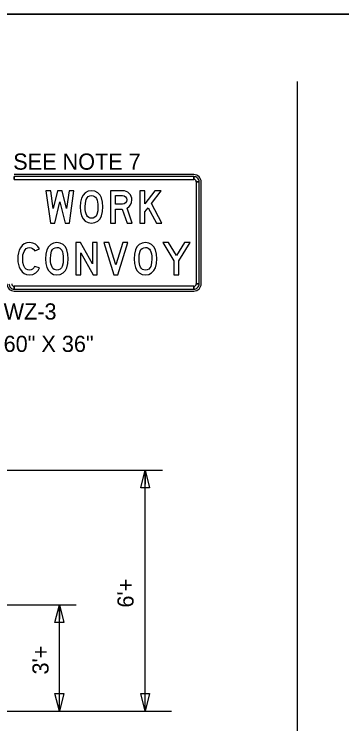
# Model space of a CAD drawing. Extents: x 1374027 to 1374537, y 380415 to 381405.
# Drawn here: x 1374130.82 to 1374142.97, y 381378.88 to 381405.17 of the extents above; entities that cross this region are included whole.
import ezdxf

# ---------------------------------------------------------------- set-up
doc = ezdxf.new("R2010")
doc.units = 0
doc.layers.add('DSN_DRFT_Junk-No-Plot', color=7, linetype='Continuous')
doc.layers.add('Working Level 1', color=7, linetype='Continuous')

msp = doc.modelspace()

# ---------------------------------------------------------------- linework, layer by layer
at = {"layer": 'DSN_DRFT_Junk-No-Plot'}
for points in [[(1374027.083, 381405.174), (1374197.083, 381405.174), (1374197.083, 381295.174), (1374027.083, 381295.174)], [(1374027.083, 381405.174), (1374027.083, 381295.174), (1374197.083, 381295.174), (1374197.083, 381405.174)]]:
    msp.add_lwpolyline(points, close=True, dxfattribs=at)
at = {"layer": 'Working Level 1'}
for p, q in [((1374141.313, 381402.674), (1374141.313, 381297.674)), ((1374137.485, 381399.231), (1374130.825, 381399.231)), ((1374130.825, 381399.051), (1374130.825, 381399.156)), ((1374137.485, 381399.156), (1374137.485, 381399.051)), ((1374137.575, 381398.961), (1374137.679, 381398.961)), ((1374137.754, 381395.181), (1374137.754, 381398.961)), ((1374130.825, 381394.986), (1374130.825, 381395.091)), ((1374137.485, 381395.091), (1374137.485, 381394.986)), ((1374137.679, 381395.181), (1374137.575, 381395.181)), ((1374130.825, 381394.911), (1374137.485, 381394.911)), ((1374129.989, 381388.277), (1374136.317, 381388.277)), ((1374135.68, 381379.345), (1374135.68, 381388.277)), ((1374135.68, 381388.277), (1374135.68, 381387.753)), ((1374130.055, 381383.287), (1374133.116, 381383.287)), ((1374132.499, 381379.345), (1374132.499, 381383.287)), ((1374132.499, 381383.287), (1374132.499, 381382.755)), ((1374118.649, 381379.345), (1374136.66, 381379.345))]:
    msp.add_line(p, q, dxfattribs=at)
for points in [[(1374137.485, 381399.156), (1374130.825, 381399.156), (1374130.825, 381399.051), (1374137.485, 381399.051), (1374137.485, 381399.156)], [(1374137.679, 381395.181), (1374137.679, 381398.961), (1374137.575, 381398.961), (1374137.575, 381395.181), (1374137.679, 381395.181)], [(1374133.041, 381398.631), (1374132.858, 381398.631), (1374132.766, 381397.973), (1374132.607, 381398.631), (1374132.432, 381398.631), (1374132.273, 381397.972), (1374132.182, 381398.631), (1374131.998, 381398.631), (1374132.166, 381397.431), (1374132.33, 381397.431), (1374132.52, 381398.22), (1374132.71, 381397.431), (1374132.873, 381397.431)], [(1374134.111, 381398.031), (1374134.099, 381398.203), (1374134.062, 381398.363), (1374134.008, 381398.471), (1374133.922, 381398.557), (1374133.813, 381398.612), (1374133.691, 381398.631), (1374133.569, 381398.612), (1374133.461, 381398.557), (1374133.376, 381398.471), (1374133.322, 381398.362), (1374133.285, 381398.202), (1374133.273, 381398.031), (1374133.285, 381397.861), (1374133.322, 381397.701), (1374133.376, 381397.592), (1374133.461, 381397.506), (1374133.569, 381397.449), (1374133.691, 381397.431), (1374133.813, 381397.449), (1374133.921, 381397.505), (1374134.007, 381397.59), (1374134.061, 381397.699), (1374134.098, 381397.86)], [(1374135.199, 381397.431), (1374135.01, 381397.991), (1374135.084, 381398.043), (1374135.141, 381398.115), (1374135.178, 381398.201), (1374135.191, 381398.294), (1374135.184, 381398.36), (1374135.166, 381398.422), (1374135.134, 381398.479), (1374135.091, 381398.532), (1374135.038, 381398.575), (1374134.981, 381398.606), (1374134.918, 381398.624), (1374134.851, 381398.631), (1374134.398, 381398.631), (1374134.398, 381397.431), (1374134.579, 381397.431), (1374134.579, 381397.952), (1374134.831, 381397.952), (1374135.008, 381397.431)], [(1374136.299, 381397.431), (1374135.909, 381398.162), (1374136.27, 381398.631), (1374136.041, 381398.631), (1374135.667, 381398.145), (1374135.667, 381398.631), (1374135.486, 381398.631), (1374135.486, 381397.431), (1374135.667, 381397.431), (1374135.667, 381397.848), (1374135.788, 381398.004), (1374136.094, 381397.431)], [(1374133.93, 381398.031), (1374133.919, 381397.885), (1374133.887, 381397.749), (1374133.858, 381397.693), (1374133.813, 381397.649), (1374133.757, 381397.621), (1374133.693, 381397.612), (1374133.637, 381397.618), (1374133.588, 381397.638), (1374133.547, 381397.671), (1374133.514, 381397.717), (1374133.488, 381397.775), (1374133.469, 381397.847), (1374133.458, 381397.932), (1374133.454, 381398.031), (1374133.465, 381398.176), (1374133.497, 381398.311), (1374133.525, 381398.368), (1374133.57, 381398.412), (1374133.627, 381398.44), (1374133.693, 381398.45), (1374133.748, 381398.443), (1374133.796, 381398.423), (1374133.837, 381398.391), (1374133.87, 381398.345), (1374133.896, 381398.286), (1374133.915, 381398.214), (1374133.926, 381398.129)], [(1374134.579, 381398.133), (1374134.579, 381398.45), (1374134.843, 381398.45), (1374134.901, 381398.438), (1374134.95, 381398.403), (1374134.983, 381398.351), (1374134.994, 381398.291), (1374134.983, 381398.23), (1374134.95, 381398.179), (1374134.901, 381398.144), (1374134.843, 381398.133)], [(1374131.759, 381395.777), (1374131.577, 381395.823), (1374131.55, 381395.77), (1374131.506, 381395.729), (1374131.45, 381395.701), (1374131.388, 381395.692), (1374131.325, 381395.701), (1374131.27, 381395.73), (1374131.225, 381395.778), (1374131.188, 381395.845), (1374131.151, 381395.968), (1374131.139, 381396.111), (1374131.151, 381396.254), (1374131.189, 381396.378), (1374131.227, 381396.444), (1374131.274, 381396.491), (1374131.329, 381396.52), (1374131.394, 381396.53), (1374131.453, 381396.521), (1374131.508, 381396.496), (1374131.554, 381396.457), (1374131.585, 381396.407), (1374131.759, 381396.475), (1374131.7, 381396.571), (1374131.614, 381396.646), (1374131.51, 381396.694), (1374131.396, 381396.711), (1374131.291, 381396.698), (1374131.199, 381396.661), (1374131.12, 381396.598), (1374131.054, 381396.511), (1374131.012, 381396.424), (1374130.982, 381396.329), (1374130.964, 381396.224), (1374130.958, 381396.111), (1374130.963, 381395.999), (1374130.981, 381395.895), (1374131.011, 381395.799), (1374131.053, 381395.713), (1374131.117, 381395.624), (1374131.195, 381395.561), (1374131.286, 381395.523), (1374131.39, 381395.511), (1374131.512, 381395.529), (1374131.622, 381395.585), (1374131.708, 381395.67)], [(1374132.827, 381396.111), (1374132.814, 381396.283), (1374132.778, 381396.443), (1374132.724, 381396.551), (1374132.638, 381396.637), (1374132.529, 381396.692), (1374132.407, 381396.711), (1374132.285, 381396.692), (1374132.177, 381396.637), (1374132.092, 381396.551), (1374132.038, 381396.442), (1374132.001, 381396.282), (1374131.989, 381396.111), (1374132.001, 381395.941), (1374132.038, 381395.781), (1374132.092, 381395.672), (1374132.177, 381395.586), (1374132.285, 381395.529), (1374132.407, 381395.511), (1374132.529, 381395.529), (1374132.637, 381395.585), (1374132.723, 381395.67), (1374132.777, 381395.779), (1374132.814, 381395.94)], [(1374133.906, 381395.511), (1374133.906, 381396.711), (1374133.725, 381396.711), (1374133.725, 381395.922), (1374133.288, 381396.711), (1374133.114, 381396.711), (1374133.114, 381395.511), (1374133.295, 381395.511), (1374133.295, 381396.325), (1374133.746, 381395.511)], [(1374135.039, 381396.711), (1374134.849, 381396.711), (1374134.592, 381395.882), (1374134.334, 381396.711), (1374134.145, 381396.711), (1374134.517, 381395.511), (1374134.666, 381395.511)], [(1374136.108, 381396.111), (1374136.095, 381396.283), (1374136.059, 381396.443), (1374136.005, 381396.551), (1374135.919, 381396.637), (1374135.81, 381396.692), (1374135.688, 381396.711), (1374135.566, 381396.692), (1374135.458, 381396.637), (1374135.373, 381396.551), (1374135.319, 381396.442), (1374135.282, 381396.282), (1374135.27, 381396.111), (1374135.282, 381395.941), (1374135.319, 381395.781), (1374135.373, 381395.672), (1374135.458, 381395.586), (1374135.566, 381395.529), (1374135.688, 381395.511), (1374135.81, 381395.529), (1374135.918, 381395.585), (1374136.004, 381395.67), (1374136.058, 381395.779), (1374136.095, 381395.94)], [(1374137.345, 381396.711), (1374137.132, 381396.711), (1374136.838, 381396.232), (1374136.55, 381396.711), (1374136.339, 381396.711), (1374136.746, 381396.036), (1374136.746, 381395.511), (1374136.927, 381395.511), (1374136.927, 381396.032)], [(1374132.646, 381396.111), (1374132.635, 381395.965), (1374132.603, 381395.829), (1374132.574, 381395.773), (1374132.529, 381395.729), (1374132.473, 381395.701), (1374132.409, 381395.692), (1374132.352, 381395.698), (1374132.304, 381395.718), (1374132.263, 381395.751), (1374132.23, 381395.797), (1374132.203, 381395.855), (1374132.185, 381395.927), (1374132.174, 381396.012), (1374132.17, 381396.111), (1374132.181, 381396.256), (1374132.213, 381396.391), (1374132.241, 381396.448), (1374132.286, 381396.492), (1374132.343, 381396.52), (1374132.409, 381396.53), (1374132.464, 381396.523), (1374132.512, 381396.503), (1374132.553, 381396.471), (1374132.586, 381396.425), (1374132.612, 381396.366), (1374132.631, 381396.294), (1374132.642, 381396.209)], [(1374135.927, 381396.111), (1374135.916, 381395.965), (1374135.884, 381395.829), (1374135.855, 381395.773), (1374135.81, 381395.729), (1374135.754, 381395.701), (1374135.69, 381395.692), (1374135.633, 381395.698), (1374135.585, 381395.718), (1374135.544, 381395.751), (1374135.511, 381395.797), (1374135.485, 381395.855), (1374135.466, 381395.927), (1374135.455, 381396.012), (1374135.451, 381396.111), (1374135.462, 381396.256), (1374135.494, 381396.391), (1374135.522, 381396.448), (1374135.567, 381396.492), (1374135.624, 381396.52), (1374135.69, 381396.53), (1374135.745, 381396.523), (1374135.793, 381396.503), (1374135.834, 381396.471), (1374135.867, 381396.425), (1374135.893, 381396.366), (1374135.912, 381396.294), (1374135.923, 381396.209)], [(1374130.825, 381394.986), (1374137.485, 381394.986), (1374137.485, 381395.091), (1374130.825, 381395.091), (1374130.825, 381394.986)], [(1374135.518, 381387.627), (1374135.68, 381388.277), (1374135.843, 381387.627)], [(1374132.337, 381382.637), (1374132.499, 381383.287), (1374132.662, 381382.637)], [(1374132.662, 381379.995), (1374132.499, 381379.345), (1374132.337, 381379.995)], [(1374135.843, 381379.995), (1374135.68, 381379.345), (1374135.518, 381379.995)]]:
    msp.add_lwpolyline(points, close=True, dxfattribs=at)
for centre, radius, start, end in [((1374137.485, 381398.961), 0.27, 0, 90.0002), ((1374137.485, 381398.961), 0.195, 0, 90.0002), ((1374137.485, 381398.961), 0.09, 0, 90.0002), ((1374130.825, 381395.181), 0.27, 179.9998, 270.0001), ((1374130.825, 381395.181), 0.195, 179.9998, 270.0001), ((1374130.825, 381395.181), 0.09, 179.9998, 270.0001), ((1374137.485, 381395.181), 0.27, 270.0001, 0.0003), ((1374137.485, 381395.181), 0.195, 270.0001, 0.0003), ((1374137.485, 381395.181), 0.09, 270.0001, 0.0003)]:
    msp.add_arc(centre, radius, start, end, dxfattribs=at)

# ---------------------------------------------------------------- texts
msp.add_text('SEE NOTE 7 ', height=0.6, dxfattribs=at).set_placement((1374130.789, 381399.411))
for s, rotation, p in [('WZ-3', 0, (1374130.433, 381393.858)), ('60" X 36"', 0, (1374130.433, 381392.658)), ("6'+", 90, (1374135.251, 381383.185)), ("3'+", 90, (1374132.1, 381380.705))]:
    msp.add_text(s, height=0.6, rotation=rotation, dxfattribs=at).set_placement(p)

doc.saveas('drawing.dxf')
